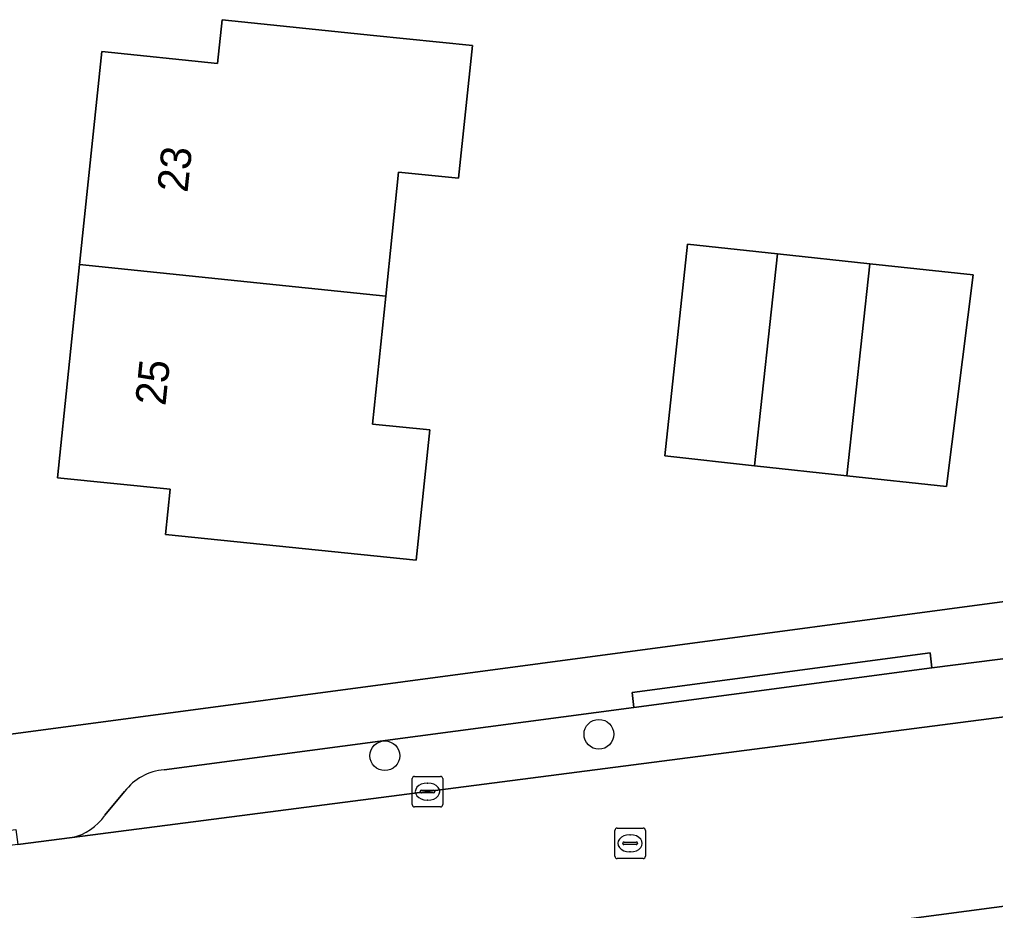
# Model space of a CAD drawing. Extents: x 162396 to 163643, y 386452 to 387406.
# Drawn here: x 162787.92 to 162819.96, y 386524.4 to 386553.66 of the extents above; entities that cross this region are included whole.
import ezdxf

# ---------------------------------------------------------------- set-up
doc = ezdxf.new("R2010")
doc.units = 0
for name, color, linetype in [('IMGEO_Boom', 7, 'Continuous'), ('IMGEO_Erf', 7, 'Continuous'), ('IMGEO_Kolk', 7, 'Continuous'), ('IMGEO_Pand', 7, 'Continuous'), ('IMGEO_Pand_nummerreeks', 7, 'Continuous'), ('IMGEO_Parkeervlak_open', 7, 'Continuous'), ('IMGEO_Rijbaan_lokaal_open', 7, 'Continuous'), ('IMGEO_Rioolput', 7, 'Continuous'), ('IMGEO_Voetpad_open', 7, 'Continuous')]:
    doc.layers.add(name, color=color, linetype=linetype)

msp = doc.modelspace()

# ---------------------------------------------------------------- linework, layer by layer
at = {"layer": 'IMGEO_Boom'}
for centre in [(162806.94, 386530.187), (162799.913, 386529.483)]:
    msp.add_circle(centre, 0.489, dxfattribs=at)
at = {"layer": 'IMGEO_Erf'}
msp.add_lwpolyline([(162845.859, 386583.167), (162843.932, 386583.335), (162785.824, 386587.292), (162782.993, 386561.193), (162787.136, 386530.123), (162840.749, 386537.29)], dxfattribs=at)
for points in [[(162802.787, 386552.805), (162802.337, 386548.447), (162800.365, 386548.65), (162799.944, 386544.578), (162799.51, 386540.376), (162801.389, 386540.182), (162800.947, 386535.903), (162792.715, 386536.754), (162792.868, 386538.233), (162789.173, 386538.615), (162789.896, 386545.615), (162790.62, 386552.616), (162794.424, 386552.223), (162794.572, 386553.654), (162799.546, 386553.14)], [(162818.344, 386538.324), (162815.075, 386538.679), (162812.043, 386539.009), (162809.101, 386539.329), (162809.85, 386546.288), (162812.802, 386545.97), (162815.834, 386545.643), (162819.224, 386545.278)]]:
    msp.add_lwpolyline(points, close=True, dxfattribs=at)
at = {"layer": 'IMGEO_Kolk'}
for p, q in [((162800.814, 386527.878), (162800.814, 386528.73)), ((162800.889, 386528.804), (162801.741, 386528.804)), ((162801.815, 386528.73), (162801.815, 386527.878)), ((162801.073, 386528.298), (162801.073, 386528.31)), ((162801.116, 386528.347), (162801.514, 386528.347)), ((162801.302, 386528.584), (162801.327, 386528.584)), ((162801.557, 386528.31), (162801.557, 386528.298)), ((162801.511, 386528.261), (162801.113, 386528.261)), ((162801.325, 386528.024), (162801.3, 386528.024)), ((162801.741, 386527.804), (162800.889, 386527.804))]:
    msp.add_line(p, q, dxfattribs=at)
for points in [[(162800.814, 386527.878), (162800.814, 386528.73)], [(162800.889, 386528.804), (162801.741, 386528.804)], [(162801.815, 386528.73), (162801.815, 386527.878)], [(162801.741, 386527.804), (162800.889, 386527.804)]]:
    msp.add_lwpolyline(points, dxfattribs=at)
for centre, radius, start, end in [((162800.891, 386528.728), 0.0765, 91.552, 178.448), ((162800.891, 386528.728), 0.0765, 91.552, 178.448), ((162801.739, 386528.728), 0.0765, 1.552, 88.448), ((162801.739, 386528.728), 0.0765, 1.552, 88.448), ((162801.113, 386528.307), 0.0403, 85.8775, 175.7526), ((162801.11, 386528.297), 0.0366, 178.938, 274.7102), ((162801.514, 386528.304), 0.043, 264.8664, 352.4533), ((162801.518, 386528.309), 0.0386, 1.7309, 96.639), ((162800.891, 386527.88), 0.0765, 181.552, 268.448), ((162800.891, 386527.88), 0.0765, 181.552, 268.448), ((162801.739, 386527.88), 0.0765, 271.552, 358.448), ((162801.739, 386527.88), 0.0765, 271.552, 358.448)]:
    msp.add_arc(centre, radius, start, end, dxfattribs=at)
for centre, major_axis, ratio, start_param, end_param in [((162801.301, 386528.304), (-0.387, 0.002), 0.722429, 4.712389, 7.853982), ((162801.326, 386528.304), (-0.39, 0.002), 0.717154, 1.570796, 4.712389)]:
    msp.add_ellipse(centre, major_axis=major_axis, ratio=ratio, start_param=start_param, end_param=end_param, dxfattribs=at)
at = {"layer": 'IMGEO_Pand'}
for points in [[(162799.944, 386544.578), (162800.365, 386548.65), (162802.337, 386548.447), (162802.787, 386552.805), (162799.546, 386553.14), (162794.572, 386553.654), (162794.424, 386552.223), (162790.62, 386552.616), (162789.896, 386545.615)], [(162812.802, 386545.97), (162809.85, 386546.288), (162809.101, 386539.329), (162812.043, 386539.009)], [(162812.043, 386539.009), (162815.075, 386538.679), (162815.834, 386545.643), (162812.802, 386545.97)], [(162789.896, 386545.615), (162789.173, 386538.615), (162792.868, 386538.233), (162792.715, 386536.754), (162800.947, 386535.903), (162801.389, 386540.182), (162799.51, 386540.376), (162799.944, 386544.578)], [(162815.075, 386538.679), (162818.344, 386538.324), (162819.224, 386545.278), (162815.834, 386545.643)]]:
    msp.add_lwpolyline(points, close=True, dxfattribs=at)
at = {"layer": 'IMGEO_Parkeervlak_open'}
for points in [[(162837.086, 386534.81), (162817.868, 386532.367), (162808.09, 386531.068), (162792.674, 386529.019)], [(162789.647, 386526.798), (162840.614, 386533.403)], [(162791.373, 386528.307), (162790.72, 386527.526)]]:
    msp.add_lwpolyline(points, dxfattribs=at)
for centre, radius, start, end in [((162792.793, 386527.256), 1.767, 93.8773, 143.504), ((162789.269, 386528.51), 1.754, 282.457, 325.8546)]:
    msp.add_arc(centre, radius, start, end, dxfattribs=at)
at = {"layer": 'IMGEO_Rijbaan_lokaal_open'}
for points in [[(162841.728, 386533.533), (162840.614, 386533.403), (162789.647, 386526.798), (162787.863, 386526.568), (162782.586, 386525.888), (162781.228, 386525.704), (162719.62, 386517.361), (162714.676, 386516.691)], [(162719.184, 386511.143), (162842.452, 386527.484)]]:
    msp.add_lwpolyline(points, dxfattribs=at)
at = {"layer": 'IMGEO_Rioolput'}
for p, q in [((162807.463, 386526.18), (162807.463, 386527.032)), ((162807.538, 386527.106), (162808.39, 386527.106)), ((162808.464, 386527.032), (162808.464, 386526.18)), ((162807.951, 386526.886), (162807.976, 386526.886)), ((162807.722, 386526.6), (162807.722, 386526.612)), ((162808.16, 386526.563), (162807.762, 386526.563)), ((162807.765, 386526.649), (162808.163, 386526.649)), ((162808.206, 386526.612), (162808.206, 386526.6)), ((162808.39, 386526.106), (162807.538, 386526.106)), ((162807.974, 386526.326), (162807.949, 386526.326))]:
    msp.add_line(p, q, dxfattribs=at)
for points in [[(162807.463, 386526.18), (162807.463, 386527.032)], [(162807.538, 386527.106), (162808.39, 386527.106)], [(162808.464, 386527.032), (162808.464, 386526.18)], [(162808.39, 386526.106), (162807.538, 386526.106)]]:
    msp.add_lwpolyline(points, dxfattribs=at)
for centre, radius, start, end in [((162807.54, 386527.03), 0.0765, 91.552, 178.448), ((162807.54, 386527.03), 0.0765, 91.552, 178.448), ((162808.388, 386527.03), 0.0765, 1.552, 88.448), ((162808.388, 386527.03), 0.0765, 1.552, 88.448), ((162807.762, 386526.609), 0.0403, 85.8775, 175.7526), ((162807.759, 386526.599), 0.0366, 178.938, 274.7102), ((162808.163, 386526.606), 0.043, 264.8664, 352.4533), ((162808.167, 386526.611), 0.0386, 1.7309, 96.639), ((162807.54, 386526.182), 0.0765, 181.552, 268.448), ((162807.54, 386526.182), 0.0765, 181.552, 268.448), ((162808.388, 386526.182), 0.0765, 271.552, 358.448), ((162808.388, 386526.182), 0.0765, 271.552, 358.448)]:
    msp.add_arc(centre, radius, start, end, dxfattribs=at)
for centre, major_axis, ratio, start_param, end_param in [((162807.95, 386526.606), (-0.387, 0.002), 0.722429, 4.712389, 7.853982), ((162807.975, 386526.606), (-0.39, 0.002), 0.717154, 1.570796, 4.712389)]:
    msp.add_ellipse(centre, major_axis=major_axis, ratio=ratio, start_param=start_param, end_param=end_param, dxfattribs=at)
at = {"layer": 'IMGEO_Voetpad_open'}
for points in [[(162840.749, 386537.29), (162787.136, 386530.123), (162782.057, 386529.467), (162740.423, 386523.825), (162736.952, 386523.355), (162729.846, 386522.392), (162715.646, 386520.468)], [(162792.674, 386529.019), (162808.09, 386531.068), (162808.03, 386531.564), (162817.808, 386532.863), (162817.868, 386532.367), (162837.086, 386534.81)], [(162790.72, 386527.526), (162791.373, 386528.307)], [(162842.452, 386527.484), (162719.184, 386511.143)], [(162781.228, 386525.704), (162782.586, 386525.888), (162782.527, 386526.384), (162787.804, 386527.064), (162787.863, 386526.568), (162789.647, 386526.798)]]:
    msp.add_lwpolyline(points, dxfattribs=at)
msp.add_lwpolyline([(162808.09, 386531.068), (162817.868, 386532.367), (162817.808, 386532.863), (162808.03, 386531.564)], close=True, dxfattribs=at)
for centre, radius, start, end in [((162792.793, 386527.256), 1.767, 93.8773, 143.504), ((162789.269, 386528.51), 1.754, 282.457, 325.8546)]:
    msp.add_arc(centre, radius, start, end, dxfattribs=at)

# ---------------------------------------------------------------- texts
at = {"layer": 'IMGEO_Pand_nummerreeks'}
for s, p in [('23', (162793.436, 386547.957)), ('25', (162792.712, 386540.956))]:
    msp.add_text(s, height=1, rotation=84.0994, dxfattribs=at).set_placement(p)

doc.saveas('drawing.dxf')
